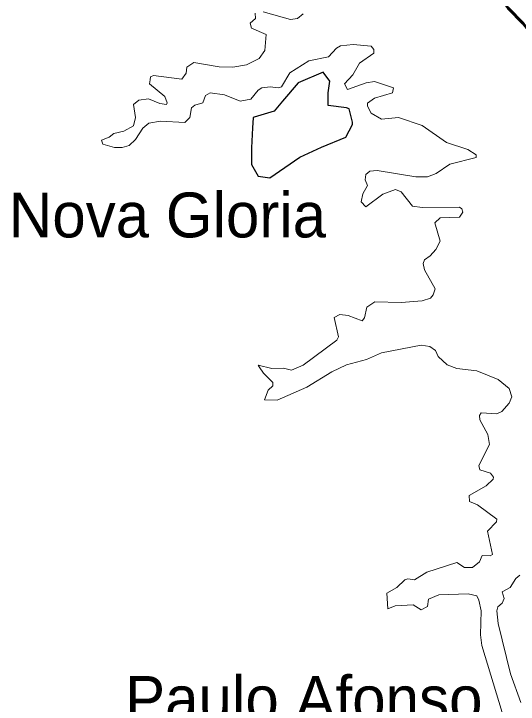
# Model space of a CAD drawing. Extents: x 553962 to 842807, y 8883888 to 9032388.
# Drawn here: x 578481 to 584093, y 8960655 to 8968341 of the extents above; entities that cross this region are included whole.
import ezdxf
from ezdxf.enums import TextEntityAlignment as Align

# ---------------------------------------------------------------- set-up
doc = ezdxf.new("R2010")
doc.units = 0
doc.header["$LTSCALE"] = 200
doc.linetypes.add('LONG_DASH_SHORT_DASH', pattern=[9.9, 6, -1.2, 1.5, -1.2])
for name, color, linetype, lineweight in [('21', 7, 'Continuous', 25), ('25', 7, 'Continuous', 13), ('7', 7, 'LONG_DASH_SHORT_DASH', 60)]:
    doc.layers.add(name, color=color, linetype=linetype, lineweight=lineweight)
doc.layers.add('41', color=7, linetype='Continuous')

msp = doc.modelspace()

# ---------------------------------------------------------------- linework, layer by layer
at = {"layer": '21'}
msp.add_lwpolyline([(581144.7, 8967182.6), (581135.4, 8967071.1), (581126.2, 8966848.2), (581126.2, 8966662.4), (581200.4, 8966532.3), (581330.4, 8966513.8), (581664.7, 8966746), (581906.1, 8966857.5), (582175.4, 8966968.9), (582249.7, 8967108.2), (582249.7, 8967136.1), (582212.6, 8967284.7), (582184.7, 8967294), (581980.4, 8967321.9), (581980.4, 8967461.2), (581999, 8967591.2), (581924.7, 8967693.4), (581646.1, 8967572.7), (581469.7, 8967368.3), (581376.9, 8967256.9), (581154, 8967191.8)], close=True, dxfattribs=at)
at = {"layer": '25'}
msp.add_line((579471.8, 8966890.6), (579467.6, 8966902.2), dxfattribs=at)
msp.add_line((579471.8, 8966890.6), (579467.6, 8966902.2), dxfattribs=at)
for points in [[(581254, 8968362.6), (581560.2, 8968277.7), (581636.5, 8968288.5), (581702.2, 8968341.5)], [(581254, 8968362.6), (581560.2, 8968277.7), (581636.5, 8968288.5), (581702.2, 8968341.5)], [(579997.9, 8967607), (580002.2, 8967641.4), (580036, 8967653.3), (580349.3, 8967615), (580399.9, 8967680.5), (580404.5, 8967748.8), (580485.3, 8967797.5), (580765.4, 8967750.9), (580918.4, 8967748.8), (581071.3, 8967774.2), (581209.4, 8967844.3), (581273.1, 8967931.4), (581290, 8968109.6), (581126.5, 8968182.3), (581109.5, 8968238.9), (581170.9, 8968290.2), (581167, 8968349.8)], [(579997.9, 8967607), (580002.2, 8967641.4), (580036, 8967653.3), (580349.3, 8967615), (580399.9, 8967680.5), (580404.5, 8967748.8), (580485.3, 8967797.5), (580765.4, 8967750.9), (580918.4, 8967748.8), (581071.3, 8967774.2), (581209.4, 8967844.3), (581273.1, 8967931.4), (581290, 8968109.6), (581126.5, 8968182.3), (581109.5, 8968238.9), (581170.9, 8968290.2), (581167, 8968349.8)], [(581209.9, 8964412.9), (581198.1, 8964430.9), (581351.7, 8964392.4), (581483.4, 8964396.6), (581572.4, 8964375.4), (581702.2, 8964430.7), (582073.9, 8964708.9), (582095.1, 8964745.1), (582044.3, 8964959.3), (582107.7, 8964995.5), (582107.7, 8964995.5), (582201.2, 8964983), (582356.2, 8964921.4), (582384.1, 8964957.7), (582407.6, 8965076.4), (582498.3, 8965133.6), (582792, 8965127.4), (583025.6, 8965146.5), (583119.2, 8965176.5), (583148.8, 8965212.4), (583170, 8965280.6), (583051.2, 8965492.5), (583034.2, 8965562.9), (583049.1, 8965601.1), (583114.8, 8965645.7), (583178, 8965717.2), (583225.2, 8965811.2), (583165.9, 8966013.2), (583223.5, 8966068.5), (583441.9, 8966077), (583475.9, 8966134.3), (583465.2, 8966170.4), (583439.6, 8966189.4), (583025.6, 8966183.2), (582915.7, 8966200), (582789.8, 8966359.4), (582728.2, 8966384.9), (582588.1, 8966331.8), (582396.7, 8966191.8), (582346, 8966247.1), (582364.9, 8966338), (582415.8, 8966429.6), (582390.2, 8966492.9), (582396.9, 8966552.7), (582441.5, 8966588.8), (582524.1, 8966597.4), (582953.4, 8966525.2), (583085.1, 8966527.3), (583178.8, 8966563.5), (583331.5, 8966667.5), (583624.5, 8966739.8), (583624.6, 8966771.3), (583531.2, 8966831), (583297.3, 8966909.8), (583025.6, 8967098.7), (582760.3, 8967185.7), (582571.1, 8967166.8), (582456.7, 8967236.5), (582416, 8967311.4), (582416.1, 8967347.1), (582494.8, 8967400.4), (582694, 8967461.9), (582706.9, 8967517.1), (582494.3, 8967589.4), (582401.1, 8967574.5), (582195.1, 8967498.2), (582159.1, 8967561.8), (582254.4, 8967663.6), (582326.8, 8967791.2), (582488.1, 8967904.1), (582488.1, 8967944.1), (582458.3, 8967980.2), (582256.4, 8967999.4), (582116.5, 8967984.5), (582071.9, 8967959), (581982.3, 8967861.3), (581763.8, 8967818.8), (581553.6, 8967684.9), (581459.8, 8967529.9), (581427.3, 8967517.2), (581332, 8967527.8), (581241.1, 8967517), (581198.8, 8967489.5), (581119.9, 8967389.7), (580998.9, 8967368.6), (580825.2, 8967438.5), (580667.5, 8967459.7), (580614.4, 8967431.8), (580582.4, 8967349.3), (580493.6, 8967323.8), (580457.7, 8967294.3), (580438.2, 8967185.8), (580385.3, 8967130.7), (580111.4, 8967147.6), (579983.5, 8967124), (579915.9, 8967069.1), (579835, 8966943.6), (579762.8, 8966875.7), (579686.3, 8966854.5), (579601.1, 8966852.3), (579471.8, 8966890.6)], [(581209.9, 8964412.9), (581198.1, 8964430.9), (581351.7, 8964392.4), (581483.4, 8964396.6), (581572.4, 8964375.4), (581702.2, 8964430.7), (582073.9, 8964708.9), (582095.1, 8964745.1), (582044.3, 8964959.3), (582107.7, 8964995.5), (582107.7, 8964995.5), (582201.2, 8964983), (582356.2, 8964921.4), (582384.1, 8964957.7), (582407.6, 8965076.4), (582498.3, 8965133.6), (582792, 8965127.4), (583025.6, 8965146.5), (583119.2, 8965176.5), (583148.8, 8965212.4), (583170, 8965280.6), (583051.2, 8965492.5), (583034.2, 8965562.9), (583049.1, 8965601.1), (583114.8, 8965645.7), (583178, 8965717.2), (583225.2, 8965811.2), (583165.9, 8966013.2), (583223.5, 8966068.5), (583441.9, 8966077), (583475.9, 8966134.3), (583465.2, 8966170.4), (583439.6, 8966189.4), (583025.6, 8966183.2), (582915.7, 8966200), (582789.8, 8966359.4), (582728.2, 8966384.9), (582588.1, 8966331.8), (582396.7, 8966191.8), (582346, 8966247.1), (582364.9, 8966338), (582415.8, 8966429.6), (582390.2, 8966492.9), (582396.9, 8966552.7), (582441.5, 8966588.8), (582524.1, 8966597.4), (582953.4, 8966525.2), (583085.1, 8966527.3), (583178.8, 8966563.5), (583331.5, 8966667.5), (583624.5, 8966739.8), (583624.6, 8966771.3), (583531.2, 8966831), (583297.3, 8966909.8), (583025.6, 8967098.7), (582760.3, 8967185.7), (582571.1, 8967166.8), (582456.7, 8967236.5), (582416, 8967311.4), (582416.1, 8967347.1), (582494.8, 8967400.4), (582694, 8967461.9), (582706.9, 8967517.1), (582494.3, 8967589.4), (582401.1, 8967574.5), (582195.1, 8967498.2), (582159.1, 8967561.8), (582254.4, 8967663.6), (582326.8, 8967791.2), (582488.1, 8967904.1), (582488.1, 8967944.1), (582458.3, 8967980.2), (582256.4, 8967999.4), (582116.5, 8967984.5), (582071.9, 8967959), (581982.3, 8967861.3), (581763.8, 8967818.8), (581553.6, 8967684.9), (581459.8, 8967529.9), (581427.3, 8967517.2), (581332, 8967527.8), (581241.1, 8967517), (581198.8, 8967489.5), (581119.9, 8967389.7), (580998.9, 8967368.6), (580825.2, 8967438.5), (580667.5, 8967459.7), (580614.4, 8967431.8), (580582.4, 8967349.3), (580493.6, 8967323.8), (580457.7, 8967294.3), (580438.2, 8967185.8), (580385.3, 8967130.7), (580111.4, 8967147.6), (579983.5, 8967124), (579915.9, 8967069.1), (579835, 8966943.6), (579762.8, 8966875.7), (579686.3, 8966854.5), (579601.1, 8966852.3), (579471.8, 8966890.6)], [(579467.6, 8966902.2), (579455.3, 8966936.2), (579541.6, 8966967.5), (579595, 8967007.3), (579704, 8967033.2), (579811.7, 8967092.6), (579835, 8967188.5), (579813.9, 8967330.2), (579873.1, 8967378.9), (579979.2, 8967396.1), (580105, 8967343), (580105, 8967343), (580181.1, 8967330.4), (580187.4, 8967349.7), (580161, 8967421.7), (579992.3, 8967561.8), (579997.9, 8967607)], [(579467.6, 8966902.2), (579455.3, 8966936.2), (579541.6, 8966967.5), (579595, 8967007.3), (579704, 8967033.2), (579811.7, 8967092.6), (579835, 8967188.5), (579813.9, 8967330.2), (579873.1, 8967378.9), (579979.2, 8967396.1), (580105, 8967343), (580105, 8967343), (580181.1, 8967330.4), (580187.4, 8967349.7), (580161, 8967421.7), (579992.3, 8967561.8), (579997.9, 8967607)], [(583013.2, 8964651.5), (582571.3, 8964568.8), (582405.6, 8964492.4), (582184.7, 8964432.8), (582018.8, 8964356.3), (581742.6, 8964184.2), (581411.2, 8964039.8), (581271.6, 8964044.5), (581311.5, 8964150.2), (581362.2, 8964201), (581362.3, 8964235), (581258.4, 8964339.1), (581209.9, 8964412.9)], [(583013.2, 8964651.5), (582571.3, 8964568.8), (582405.6, 8964492.4), (582184.7, 8964432.8), (582018.8, 8964356.3), (581742.6, 8964184.2), (581411.2, 8964039.8), (581271.6, 8964044.5), (581311.5, 8964150.2), (581362.2, 8964201), (581362.3, 8964235), (581258.4, 8964339.1), (581209.9, 8964412.9)], [(583979.3, 8960356.6), (583690.5, 8961308.2), (583675.7, 8961427), (583679.9, 8961694.8), (583656.7, 8961812.9), (583631.9, 8961861.4), (583535.2, 8961883.6), (583208.6, 8961873.1), (583093.8, 8961826.3), (583082.9, 8961741.4), (583013.1, 8961707.5), (582923.6, 8961760.4), (582724.2, 8961752), (582642.1, 8961718.4), (582632.6, 8961889.8), (582741.2, 8961953.9), (582832.4, 8962038.7), (582866.3, 8962051.4), (582940.9, 8962038.9), (583076.4, 8962125.7), (583410.3, 8962234), (583497.2, 8962176.9), (583584.3, 8962176.9), (583662.8, 8962238.5), (583692.8, 8962310.5), (583781.6, 8962306.4), (583807.2, 8962323.5), (583752.2, 8962580.2), (583853.2, 8962685.6), (583854, 8962716.3), (583639.8, 8962873.4), (583552.7, 8962911.8), (583548.2, 8962977.4), (583737.5, 8963086.2), (583815.2, 8963159.7), (583820, 8963181), (583784.2, 8963226), (583667.3, 8963264.5), (583654.7, 8963312.4), (583773.3, 8963547.2), (583756.3, 8963657.4), (583667.3, 8963822.9), (583661, 8963870), (583680, 8963897.4), (583854.1, 8963889), (583909.5, 8963912.6), (583992, 8964005.7), (584023.8, 8964077.5), (583992.3, 8964171.2), (583871.3, 8964269), (583632.9, 8964364.8), (583412.2, 8964392.4), (583302.1, 8964434.8), (583202.2, 8964526), (583174.1, 8964592.2), (583110.6, 8964638.7), (583013.2, 8964651.5)], [(583979.3, 8960356.6), (583690.5, 8961308.2), (583675.7, 8961427), (583679.9, 8961694.8), (583656.7, 8961812.9), (583631.9, 8961861.4), (583535.2, 8961883.6), (583208.6, 8961873.1), (583093.8, 8961826.3), (583082.9, 8961741.4), (583013.1, 8961707.5), (582923.6, 8961760.4), (582724.2, 8961752), (582642.1, 8961718.4), (582632.6, 8961889.8), (582741.2, 8961953.9), (582832.4, 8962038.7), (582866.3, 8962051.4), (582940.9, 8962038.9), (583076.4, 8962125.7), (583410.3, 8962234), (583497.2, 8962176.9), (583584.3, 8962176.9), (583662.8, 8962238.5), (583692.8, 8962310.5), (583781.6, 8962306.4), (583807.2, 8962323.5), (583752.2, 8962580.2), (583853.2, 8962685.6), (583854, 8962716.3), (583639.8, 8962873.4), (583552.7, 8962911.8), (583548.2, 8962977.4), (583737.5, 8963086.2), (583815.2, 8963159.7), (583820, 8963181), (583784.2, 8963226), (583667.3, 8963264.5), (583654.7, 8963312.4), (583773.3, 8963547.2), (583756.3, 8963657.4), (583667.3, 8963822.9), (583661, 8963870), (583680, 8963897.4), (583854.1, 8963889), (583909.5, 8963912.6), (583992, 8964005.7), (584023.8, 8964077.5), (583992.3, 8964171.2), (583871.3, 8964269), (583632.9, 8964364.8), (583412.2, 8964392.4), (583302.1, 8964434.8), (583202.2, 8964526), (583174.1, 8964592.2), (583110.6, 8964638.7), (583013.2, 8964651.5)], [(584113.2, 8962091.9), (584066.4, 8962055.5), (584002.7, 8961956), (583913.8, 8961907.2), (583936.8, 8961830.6), (583913.5, 8961781.7), (583866.6, 8961740.8), (583856.2, 8961694.6), (583869, 8961554.4), (584009.2, 8960993.4), (584121.2, 8960674.7)], [(584113.2, 8962091.9), (584066.4, 8962055.5), (584002.7, 8961956), (583913.8, 8961907.2), (583936.8, 8961830.6), (583913.5, 8961781.7), (583866.6, 8961740.8), (583856.2, 8961694.6), (583869, 8961554.4), (584009.2, 8960993.4), (584121.2, 8960674.7)]]:
    msp.add_lwpolyline(points, dxfattribs=at)
at = {"layer": '7'}
msp.add_lwpolyline([(583174.4, 8969966), (583327.9, 8969505.4), (583474.7, 8969160.4), (583725.5, 8968684.8), (583883.2, 8968539.9), (583982.9, 8968403.5), (584146.9, 8968235.1), (584624.8, 8967616.6), (584992.2, 8967072.1), (585186.8, 8966825.7), (585377.2, 8966655.9), (585748.8, 8966438.6), (585960.5, 8966257.3), (586351.6, 8965976.8), (586551, 8965796.4), (587006.6, 8965310.9), (587303.1, 8964815.2), (587426.7, 8964495.3)], dxfattribs=at)

# ---------------------------------------------------------------- texts
at = {"layer": '41'}
for s, p in [('Nova Gloria', (580191.1, 8965851.8)), ('Paulo Afonso', (581707.6, 8960468.8))]:
    msp.add_text(s, height=500, dxfattribs=at).set_placement(p, align=Align.CENTER)

doc.saveas('drawing.dxf')
